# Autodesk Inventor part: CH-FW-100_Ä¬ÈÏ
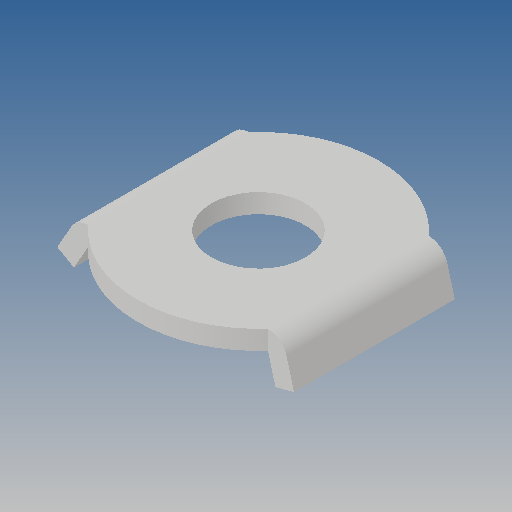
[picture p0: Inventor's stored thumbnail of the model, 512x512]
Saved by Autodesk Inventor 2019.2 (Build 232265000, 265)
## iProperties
Created: 2010-06
Part Number: CH-FW-100_Ä¬ÈÏ
Material: Ogólny
Document SubType Name: Modeling
Designer: CADENGINEERING4
Density: 1 g/cm^3
Appearance: Domyślna
Author: CADENGINEERING4
Revision Number: ÈÎºÎ
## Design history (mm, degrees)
feature "NONE"
node "Bryła1"
